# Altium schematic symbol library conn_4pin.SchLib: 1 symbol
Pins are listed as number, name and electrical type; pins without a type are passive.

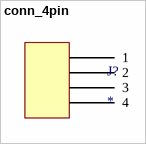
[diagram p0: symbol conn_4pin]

## conn_4pin
designator J?
footprint conn_4pin
pins: 1, 2, 3, 4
